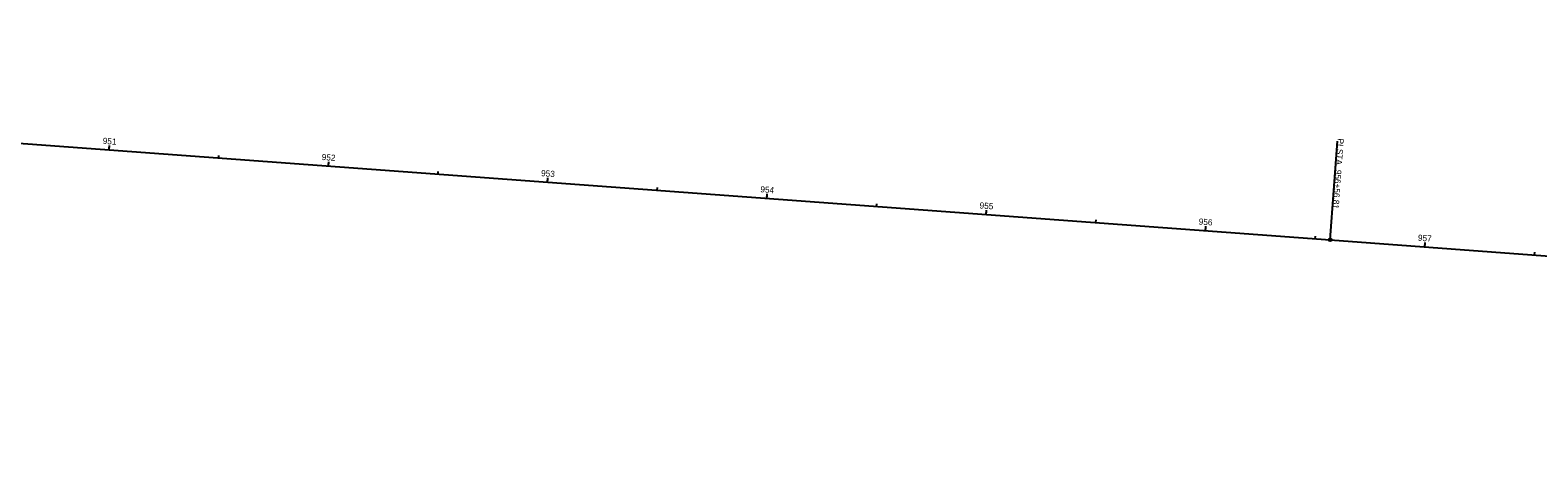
# Model space of a CAD drawing. Extents: x 1981066 to 1984208, y 708139 to 709503.
# Drawn here: x 1981769 to 1982455, y 708870 to 709064 of the extents above; entities that cross this region are included whole.
import ezdxf

# ---------------------------------------------------------------- set-up
doc = ezdxf.new("R2010")
doc.units = 0
for name, color, linetype in [('PM_X_Edge_Line', 7, 'Continuous'), ('PV_P_EOP', 7, 'Continuous'), ('PV_X_EOP', 7, 'Continuous'), ('RD_X_Wall', 7, 'Continuous'), ('SV_P_Mon_Cells_Set', 7, 'Continuous'), ('SV_X_Break_Lines', 7, 'Continuous'), ('TopoDOT Temp', 7, 'Continuous')]:
    doc.layers.add(name, color=color, linetype=linetype)

msp = doc.modelspace()

# ---------------------------------------------------------------- linework, layer by layer
at = {"layer": 'PM_X_Edge_Line'}
for p, q in [((1981805.37, 709009.45), (1981805.52, 709011.45)), ((1981855.24, 709005.78), (1981855.32, 709006.98)), ((1981905.1, 709002.11), (1981905.25, 709004.11)), ((1981954.97, 708998.44), (1981955.05, 708999.64)), ((1982004.83, 708994.77), (1982004.98, 708996.77)), ((1982054.7, 708991.1), (1982054.78, 708992.3)), ((1982104.56, 708987.43), (1982104.71, 708989.43)), ((1982154.43, 708983.76), (1982154.52, 708984.96)), ((1982204.29, 708980.09), (1982204.44, 708982.09)), ((1982254.16, 708976.42), (1982254.25, 708977.62)), ((1982304.02, 708972.75), (1982304.17, 708974.75)), ((1982353.89, 708969.08), (1982353.98, 708970.28)), ((1982403.75, 708965.41), (1982403.9, 708967.41)), ((1982453.62, 708961.74), (1982453.71, 708962.94))]:
    msp.add_line(p, q, dxfattribs=at)
at = {"layer": 'PV_P_EOP'}
msp.add_line((1982204.29, 708980.09), (1982204.38, 708981.29), dxfattribs=at)
at = {"layer": 'PV_X_EOP'}
msp.add_line((1982360.68, 708968.58), (1982363.98, 709013.46), dxfattribs=at)
msp.add_circle((1982360.68, 708968.58), 0.6, dxfattribs=at)
at = {"layer": 'RD_X_Wall'}
for p, q in [((1981805.37, 709009.45), (1981805.46, 709010.65)), ((1981905.1, 709002.11), (1981905.19, 709003.31)), ((1982004.83, 708994.77), (1982004.92, 708995.97)), ((1982104.56, 708987.43), (1982104.65, 708988.63)), ((1982204.29, 708980.09), (1982204.44, 708982.09)), ((1982304.02, 708972.75), (1982304.11, 708973.95)), ((1982403.75, 708965.41), (1982403.84, 708966.61))]:
    msp.add_line(p, q, dxfattribs=at)
at = {"layer": 'SV_P_Mon_Cells_Set'}
msp.add_line((1982360.68, 708968.58), (1982363.98, 709013.46), dxfattribs=at)
msp.add_circle((1982360.68, 708968.58), 0.6, dxfattribs=at)
at = {"layer": 'SV_X_Break_Lines'}
for p, q in [((1981066.12, 709063.86), (1982360.68, 708968.58)), ((1981066.12, 709063.86), (1982360.68, 708968.58)), ((1982360.68, 708968.58), (1983700.25, 708869.99))]:
    msp.add_line(p, q, dxfattribs=at)
at = {"layer": 'TopoDOT Temp'}
msp.add_line((1982360.68, 708968.58), (1982363.98, 709013.46), dxfattribs=at)
msp.add_circle((1982360.68, 708968.58), 0.6, dxfattribs=at)

# ---------------------------------------------------------------- texts
at = {"layer": 'PM_X_Edge_Line'}
for s, p in [('951', (1981802.42, 709012.22)), ('952', (1981902.02, 709004.89)), ('953', (1982001.76, 708997.55)), ('954', (1982101.49, 708990.21)), ('955', (1982201.18, 708982.87)), ('956', (1982300.86, 708975.54)), ('957', (1982400.53, 708968.2))]:
    msp.add_text(s, height=2.8, rotation=355.79057, dxfattribs=at).set_placement(p)
at = {"layer": 'PV_X_EOP'}
for s, p in [('PI', (1982364.13, 709014.74)), (' STA. ', (1982363.85, 709011.05)), ('956+56.81', (1982363.08, 709000.5))]:
    msp.add_text(s, height=2.8, rotation=265.79057, dxfattribs=at).set_placement(p)
at = {"layer": 'RD_X_Wall'}
msp.add_text('955', height=2.8, rotation=355.79057, dxfattribs=at).set_placement((1982201.18, 708982.87))
at = {"layer": 'SV_P_Mon_Cells_Set'}
for s, p in [('PI', (1982364.13, 709014.74)), (' STA. ', (1982363.85, 709011.05)), ('956+56.81', (1982363.08, 709000.5))]:
    msp.add_text(s, height=2.8, rotation=265.79057, dxfattribs=at).set_placement(p)
at = {"layer": 'TopoDOT Temp'}
for s, p in [('PI', (1982364.13, 709014.74)), (' STA. ', (1982363.85, 709011.05)), ('956+56.81', (1982363.08, 709000.5))]:
    msp.add_text(s, height=2.8, rotation=265.79057, dxfattribs=at).set_placement(p)

doc.saveas('drawing.dxf')
